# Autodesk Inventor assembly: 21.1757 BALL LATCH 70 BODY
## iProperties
Created: 2007-07
Part Number: 21.1757 BALL LATCH 70 BODY
Document SubType Name: Assembly
Designer: Andy Moles
Author: Andy Moles
